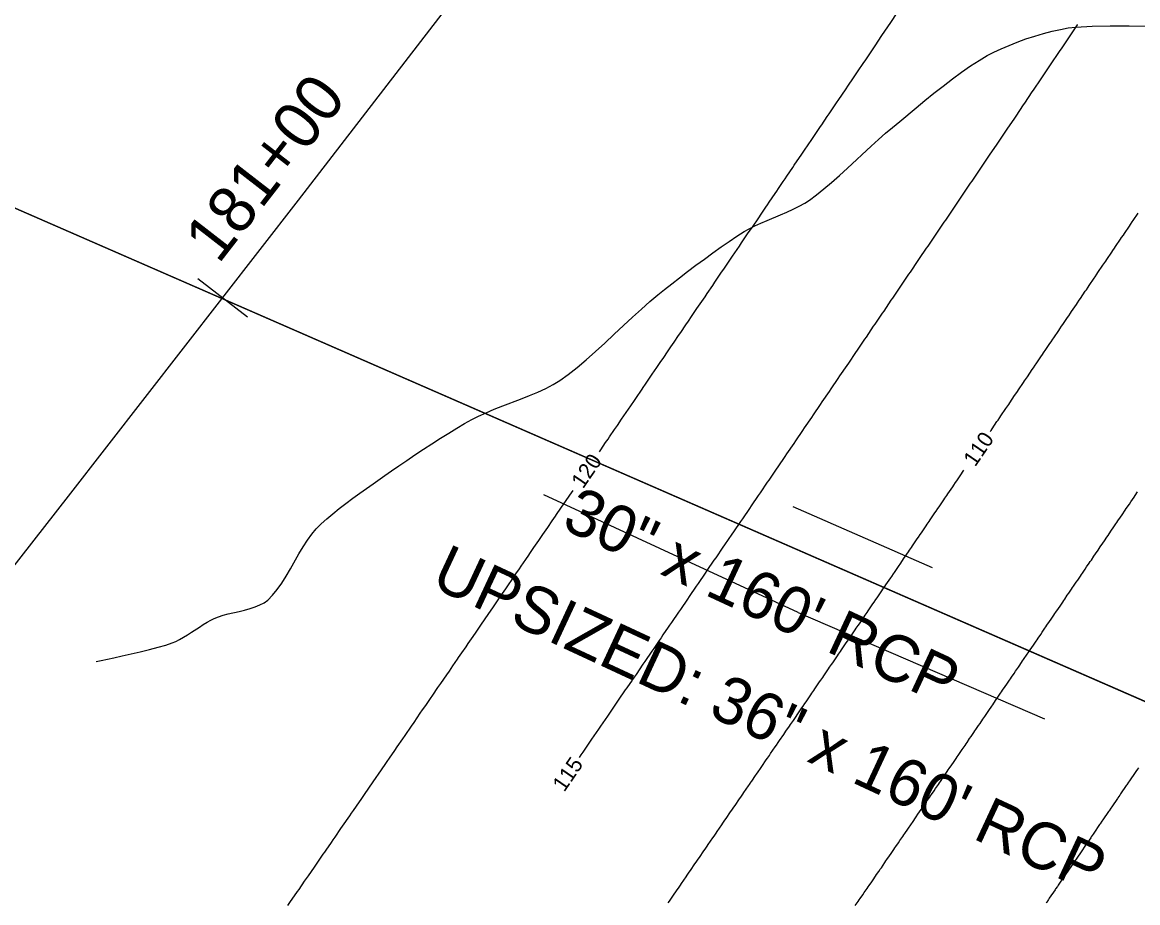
# Model space of a CAD drawing. Extents: x 1752788 to 1754108, y 472767 to 474963.
# Drawn here: x 1753208.6 to 1753280, y 473747.6 to 473804 of the extents above; entities that cross this region are included whole.
import ezdxf

# ---------------------------------------------------------------- set-up
doc = ezdxf.new("R2010")
doc.units = 0
for name, color, linetype in [('D_Drainage_Culvert', 7, 'Continuous'), ('D_Drainage_Text', 7, 'Continuous'), ('D_Roadway_Centerline', 7, 'Continuous'), ('D_Roadway_Centerline_Text', 7, 'Continuous'), ('Default', 7, 'Continuous'), ('M_Drainage_Ditch_Line', 7, 'Continuous'), ('S_Contours_Major', 7, 'Continuous')]:
    doc.layers.add(name, color=color, linetype=linetype)

msp = doc.modelspace()

# ---------------------------------------------------------------- linework, layer by layer
at = {"layer": 'D_Drainage_Culvert'}
for p, q in [((1753148.958, 473817.925), (1753295.6, 473753.923)), ((1753257.905, 473773.008), (1753266.845, 473769.099))]:
    msp.add_line(p, q, dxfattribs=at)
at = {"layer": 'D_Roadway_Centerline'}
msp.add_arc((1748084.974, 477769.754), 6500, 316.3419444, 334.4169444, dxfattribs=at)
at = {"layer": 'D_Roadway_Centerline_Text'}
msp.add_lwpolyline([(1753219.807, 473787.608), (1753222.968, 473785.156)], dxfattribs=at)
at = {"layer": 'Default'}
for p, q in [((1753295.6, 473753.923), (1753145.826, 473819.295)), ((1753258.251, 473766.217), (1753241.958, 473773.75)), ((1753258.251, 473766.217), (1753274.02, 473759.402))]:
    msp.add_line(p, q, dxfattribs=at)
at = {"layer": 'M_Drainage_Ditch_Line'}
msp.add_lwpolyline([(1753213.279, 473763.079), (1753213.598, 473763.144), (1753214.414, 473763.317), (1753214.944, 473763.433), (1753215.519, 473763.562), (1753216.113, 473763.702), (1753216.7, 473763.847), (1753217.255, 473763.993), (1753217.749, 473764.136), (1753218.159, 473764.272), (1753218.386, 473764.367), (1753218.625, 473764.488), (1753218.872, 473764.629), (1753219.126, 473764.785), (1753219.382, 473764.95), (1753219.895, 473765.288), (1753220.145, 473765.449), (1753220.389, 473765.599), (1753220.623, 473765.731), (1753220.846, 473765.841), (1753221.115, 473765.946), (1753221.418, 473766.039), (1753221.746, 473766.125), (1753222.443, 473766.29), (1753222.796, 473766.377), (1753223.141, 473766.472), (1753223.469, 473766.58), (1753223.773, 473766.703), (1753224.044, 473766.847), (1753224.274, 473767.015), (1753224.582, 473767.324), (1753224.88, 473767.692), (1753225.17, 473768.105), (1753225.452, 473768.552), (1753225.729, 473769.02), (1753226.275, 473769.97), (1753226.548, 473770.428), (1753226.822, 473770.857), (1753227.1, 473771.245), (1753227.384, 473771.581), (1753227.696, 473771.894), (1753228.051, 473772.216), (1753228.439, 473772.546), (1753228.853, 473772.878), (1753229.285, 473773.209), (1753229.726, 473773.537), (1753230.167, 473773.857), (1753230.602, 473774.165), (1753231.021, 473774.459), (1753231.78, 473774.99), (1753232.211, 473775.292), (1753232.682, 473775.617), (1753233.183, 473775.96), (1753233.706, 473776.314), (1753234.245, 473776.672), (1753234.79, 473777.029), (1753235.333, 473777.379), (1753235.868, 473777.715), (1753236.386, 473778.031), (1753236.878, 473778.321), (1753237.338, 473778.579), (1753237.776, 473778.8), (1753238.264, 473779.018), (1753238.789, 473779.234), (1753239.34, 473779.45), (1753240.475, 473779.888), (1753241.036, 473780.112), (1753241.579, 473780.341), (1753242.092, 473780.578), (1753242.563, 473780.823), (1753242.982, 473781.078), (1753243.521, 473781.463), (1753244.085, 473781.909), (1753244.669, 473782.401), (1753245.264, 473782.929), (1753245.866, 473783.479), (1753246.468, 473784.04), (1753247.064, 473784.599), (1753247.648, 473785.143), (1753248.212, 473785.66), (1753248.752, 473786.139), (1753249.262, 473786.566), (1753249.688, 473786.907), (1753250.153, 473787.274), (1753250.65, 473787.66), (1753251.169, 473788.058), (1753251.704, 473788.461), (1753252.247, 473788.863), (1753252.789, 473789.257), (1753253.322, 473789.636), (1753253.838, 473789.994), (1753254.33, 473790.324), (1753254.79, 473790.619), (1753255.11, 473790.803), (1753255.469, 473790.984), (1753255.857, 473791.162), (1753256.266, 473791.339), (1753257.11, 473791.693), (1753257.529, 473791.873), (1753257.934, 473792.055), (1753258.317, 473792.242), (1753258.668, 473792.435), (1753258.979, 473792.634), (1753259.429, 473792.968), (1753259.903, 473793.351), (1753260.394, 473793.771), (1753260.898, 473794.218), (1753261.407, 473794.684), (1753262.917, 473796.087), (1753263.396, 473796.523), (1753263.853, 473796.928), (1753264.284, 473797.29), (1753264.754, 473797.675), (1753265.803, 473798.544), (1753266.367, 473799.008), (1753266.948, 473799.478), (1753267.538, 473799.945), (1753268.13, 473800.4), (1753268.715, 473800.831), (1753269.288, 473801.231), (1753269.839, 473801.589), (1753270.363, 473801.896), (1753270.784, 473802.114), (1753271.252, 473802.334), (1753271.757, 473802.551), (1753272.289, 473802.761), (1753272.841, 473802.961), (1753273.401, 473803.146), (1753273.962, 473803.313), (1753274.515, 473803.458), (1753275.049, 473803.576), (1753275.556, 473803.664), (1753276.027, 473803.718), (1753277.088, 473803.779), (1753278.24, 473803.808), (1753279.464, 473803.81), (1753280.738, 473803.789)], dxfattribs=at)
at = {"layer": 'S_Contours_Major'}
for points in [[(1753245.517, 473776.51), (1753245.604, 473776.638), (1753245.92, 473777.101), (1753246.076, 473777.329), (1753246.169, 473777.466), (1753246.492, 473777.94), (1753246.674, 473778.206), (1753246.938, 473778.594), (1753247.24, 473779.036), (1753247.526, 473779.455), (1753247.764, 473779.805), (1753247.891, 473779.991), (1753248.208, 473780.457), (1753248.373, 473780.698), (1753248.428, 473780.779), (1753248.736, 473781.232), (1753248.907, 473781.482), (1753249.198, 473781.909), (1753249.46, 473782.295), (1753249.595, 473782.492), (1753249.923, 473782.974), (1753250.095, 473783.227), (1753250.312, 473783.546), (1753250.59, 473783.955), (1753250.73, 473784.16), (1753251.065, 473784.653), (1753251.225, 473784.887), (1753251.425, 473785.183), (1753251.768, 473785.686), (1753251.982, 473786.001), (1753252.284, 473786.445), (1753252.432, 473786.663), (1753252.777, 473787.171), (1753252.918, 473787.379), (1753253.348, 473788.011), (1753253.483, 473788.209), (1753253.918, 473788.851), (1753254.047, 473789.04), (1753254.488, 473789.691), (1753254.628, 473789.896), (1753255.059, 473790.531), (1753255.19, 473790.724), (1753255.319, 473790.914), (1753255.722, 473791.509), (1753255.875, 473791.733), (1753256.176, 473792.178), (1753256.287, 473792.341), (1753256.397, 473792.504), (1753256.768, 473793.051), (1753256.878, 473793.213), (1753256.986, 473793.372), (1753257.301, 473793.837), (1753257.415, 473794.005), (1753257.529, 473794.174), (1753257.907, 473794.731), (1753258.003, 473794.873), (1753258.479, 473795.576), (1753258.564, 473795.702), (1753258.651, 473795.83), (1753259.117, 473796.517), (1753259.206, 473796.65), (1753259.68, 473797.349), (1753259.761, 473797.469), (1753260.111, 473797.987), (1753260.234, 473798.168), (1753260.357, 473798.349), (1753260.752, 473798.934), (1753260.812, 473799.023), (1753261.321, 473799.775), (1753261.425, 473799.929), (1753261.796, 473800.477), (1753261.924, 473800.667), (1753262.052, 473800.856), (1753262.458, 473801.457), (1753262.533, 473801.568), (1753262.918, 473802.138), (1753263.049, 473802.333), (1753263.181, 473802.527), (1753263.618, 473803.175), (1753264.179, 473804.005), (1753264.6, 473804.63)], [(1753276.134, 473803.88), (1753276.12, 473803.859), (1753276.041, 473803.742), (1753275.558, 473803.025), (1753275.478, 473802.906), (1753275.088, 473802.328), (1753275.022, 473802.231), (1753274.927, 473802.089), (1753274.434, 473801.358), (1753274.352, 473801.236), (1753273.872, 473800.524), (1753273.789, 473800.401), (1753273.309, 473799.69), (1753273.226, 473799.566), (1753272.747, 473798.857), (1753272.662, 473798.731), (1753272.184, 473798.023), (1753272.099, 473797.896), (1753271.622, 473797.19), (1753271.535, 473797.062), (1753271.059, 473796.356), (1753270.971, 473796.227), (1753270.496, 473795.523), (1753270.407, 473795.393), (1753269.933, 473794.69), (1753269.843, 473794.558), (1753269.369, 473793.857), (1753269.279, 473793.724), (1753268.806, 473793.024), (1753268.715, 473792.89), (1753268.242, 473792.191), (1753268.15, 473792.055), (1753267.678, 473791.358), (1753267.586, 473791.221), (1753267.115, 473790.525), (1753267.021, 473790.387), (1753266.551, 473789.692), (1753266.456, 473789.553), (1753266.006, 473788.888), (1753265.926, 473788.771), (1753265.422, 473788.027), (1753265.326, 473787.885), (1753264.858, 473787.195), (1753264.761, 473787.052), (1753264.293, 473786.362), (1753264.196, 473786.218), (1753263.729, 473785.53), (1753263.63, 473785.385), (1753263.164, 473784.698), (1753263.065, 473784.551), (1753262.599, 473783.865), (1753262.499, 473783.718), (1753262.034, 473783.033), (1753261.933, 473782.884), (1753261.469, 473782.201), (1753261.367, 473782.051), (1753260.904, 473781.369), (1753260.801, 473781.218), (1753260.338, 473780.537), (1753260.234, 473780.385), (1753259.773, 473779.706), (1753259.668, 473779.552), (1753259.207, 473778.874), (1753259.101, 473778.719), (1753258.641, 473778.042), (1753258.535, 473777.886), (1753258.075, 473777.211), (1753257.968, 473777.053), (1753257.509, 473776.379), (1753257.401, 473776.221), (1753256.943, 473775.548), (1753256.84, 473775.398), (1753256.367, 473774.703), (1753256.268, 473774.558), (1753255.81, 473773.885), (1753255.699, 473773.723), (1753255.243, 473773.054), (1753255.131, 473772.891), (1753254.676, 473772.223), (1753254.564, 473772.058), (1753254.109, 473771.392), (1753253.996, 473771.226), (1753253.542, 473770.561), (1753253.428, 473770.394), (1753252.975, 473769.73), (1753252.86, 473769.562), (1753252.408, 473768.9), (1753252.292, 473768.73), (1753251.84, 473768.069), (1753251.724, 473767.898), (1753251.273, 473767.238), (1753251.155, 473767.066), (1753250.705, 473766.408), (1753250.586, 473766.235), (1753250.137, 473765.577), (1753250.018, 473765.403), (1753249.931, 473765.275), (1753249.591, 473764.779), (1753249.471, 473764.603), (1753249.351, 473764.428), (1753249.001, 473763.917), (1753248.88, 473763.74), (1753248.433, 473763.087), (1753248.311, 473762.908), (1753247.864, 473762.256), (1753247.742, 473762.077), (1753247.637, 473761.925), (1753247.615, 473761.892), (1753247.27, 473761.389), (1753247.178, 473761.254), (1753246.727, 473760.596), (1753246.603, 473760.415), (1753246.158, 473759.766), (1753246.033, 473759.584), (1753245.589, 473758.937), (1753245.463, 473758.753), (1753245.02, 473758.107), (1753244.893, 473757.922), (1753244.451, 473757.277), (1753244.323, 473757.091), (1753244.214, 473756.931)], [(1753270.55, 473777.805), (1753270.604, 473777.885), (1753270.674, 473777.988), (1753270.984, 473778.444), (1753271.054, 473778.547), (1753271.17, 473778.719), (1753271.24, 473778.822), (1753271.551, 473779.279), (1753271.62, 473779.382), (1753271.736, 473779.553), (1753271.806, 473779.655), (1753272.117, 473780.114), (1753272.186, 473780.216), (1753272.302, 473780.386), (1753272.372, 473780.489), (1753272.683, 473780.948), (1753272.752, 473781.05), (1753272.868, 473781.22), (1753272.937, 473781.323), (1753273.249, 473781.783), (1753273.318, 473781.885), (1753273.433, 473782.055), (1753273.502, 473782.156), (1753273.84, 473782.655), (1753273.865, 473782.691), (1753274.015, 473782.913), (1753274.081, 473783.01), (1753274.381, 473783.453), (1753274.45, 473783.554), (1753274.564, 473783.723), (1753274.633, 473783.824), (1753274.947, 473784.288), (1753275.015, 473784.389), (1753275.129, 473784.557), (1753275.198, 473784.658), (1753275.512, 473785.123), (1753275.581, 473785.224), (1753275.694, 473785.392), (1753275.763, 473785.493), (1753276.078, 473785.958), (1753276.146, 473786.059), (1753276.259, 473786.226), (1753276.327, 473786.327), (1753276.643, 473786.794), (1753276.711, 473786.894), (1753276.824, 473787.061), (1753276.892, 473787.161), (1753277.208, 473787.629), (1753277.276, 473787.729), (1753277.389, 473787.896), (1753277.456, 473787.996), (1753277.773, 473788.464), (1753277.841, 473788.564), (1753277.953, 473788.731), (1753278.021, 473788.83), (1753278.338, 473789.3), (1753278.405, 473789.399), (1753278.517, 473789.565), (1753278.585, 473789.665), (1753278.903, 473790.136), (1753278.97, 473790.235), (1753279.082, 473790.4), (1753279.149, 473790.5), (1753279.467, 473790.971), (1753279.534, 473791.07), (1753279.646, 473791.235), (1753279.713, 473791.334), (1753280.032, 473791.807)], [(1753249.93, 473747.621), (1753250.007, 473747.734), (1753250.137, 473747.923), (1753250.215, 473748.036), (1753250.501, 473748.453), (1753250.579, 473748.566), (1753250.708, 473748.754), (1753250.785, 473748.867), (1753251.072, 473749.285), (1753251.15, 473749.397), (1753251.278, 473749.585), (1753251.356, 473749.697), (1753251.643, 473750.116), (1753251.721, 473750.229), (1753251.849, 473750.416), (1753251.926, 473750.528), (1753252.215, 473750.948), (1753252.291, 473751.06), (1753252.419, 473751.247), (1753252.496, 473751.358), (1753252.785, 473751.78), (1753252.862, 473751.892), (1753252.99, 473752.078), (1753253.066, 473752.189), (1753253.356, 473752.612), (1753253.433, 473752.723), (1753253.56, 473752.909), (1753253.636, 473753.02), (1753253.927, 473753.444), (1753254.003, 473753.555), (1753254.13, 473753.74), (1753254.206, 473753.851), (1753254.497, 473754.276), (1753254.573, 473754.387), (1753254.7, 473754.572), (1753254.776, 473754.682), (1753255.074, 473755.118), (1753255.131, 473755.201), (1753255.244, 473755.366), (1753255.282, 473755.421), (1753255.52, 473755.768), (1753255.583, 473755.861), (1753255.686, 473756.012), (1753255.839, 473756.235), (1753255.915, 473756.345), (1753256.208, 473756.773), (1753256.284, 473756.883), (1753256.409, 473757.067), (1753256.485, 473757.177), (1753256.778, 473757.606), (1753256.853, 473757.716), (1753256.979, 473757.899), (1753257.054, 473758.009), (1753257.327, 473758.408), (1753257.465, 473758.61), (1753257.693, 473758.943), (1753257.768, 473759.052), (1753257.943, 473759.308), (1753258.117, 473759.562), (1753258.191, 473759.671), (1753258.487, 473760.104), (1753258.562, 473760.213), (1753258.686, 473760.394), (1753258.76, 473760.503), (1753259.057, 473760.937), (1753259.131, 473761.045), (1753259.255, 473761.226), (1753259.329, 473761.335), (1753259.626, 473761.77), (1753259.7, 473761.878), (1753259.823, 473762.058), (1753259.897, 473762.167), (1753260.195, 473762.603), (1753260.269, 473762.711), (1753260.392, 473762.891), (1753260.466, 473762.999), (1753260.764, 473763.436), (1753260.838, 473763.543), (1753260.961, 473763.723), (1753261.034, 473763.831), (1753261.333, 473764.269), (1753261.407, 473764.376), (1753261.529, 473764.555), (1753261.602, 473764.663), (1753261.902, 473765.102), (1753261.975, 473765.209), (1753262.097, 473765.388), (1753262.17, 473765.495), (1753262.471, 473765.935), (1753262.544, 473766.042), (1753262.665, 473766.221), (1753262.738, 473766.328), (1753263.039, 473766.769), (1753263.112, 473766.875), (1753263.233, 473767.053), (1753263.306, 473767.16), (1753263.607, 473767.602), (1753263.68, 473767.709), (1753263.801, 473767.886), (1753263.874, 473767.992), (1753264.178, 473768.439), (1753264.243, 473768.534), (1753264.351, 473768.693), (1753264.416, 473768.787), (1753264.713, 473769.224), (1753264.778, 473769.319), (1753264.936, 473769.552), (1753265.008, 473769.658), (1753265.312, 473770.103), (1753265.384, 473770.209), (1753265.504, 473770.385), (1753265.576, 473770.49), (1753265.88, 473770.937), (1753265.951, 473771.042), (1753266.071, 473771.218), (1753266.143, 473771.323), (1753266.447, 473771.771), (1753266.519, 473771.876), (1753266.638, 473772.051), (1753266.71, 473772.156), (1753267.015, 473772.605), (1753267.086, 473772.709), (1753267.205, 473772.884), (1753267.276, 473772.989), (1753267.582, 473773.439), (1753267.653, 473773.543), (1753267.772, 473773.717), (1753267.843, 473773.822), (1753268.15, 473774.273), (1753268.22, 473774.377), (1753268.339, 473774.551), (1753268.41, 473774.655), (1753268.717, 473775.107), (1753268.787, 473775.211), (1753268.871, 473775.333)], [(1753225.57, 473747.452), (1753225.698, 473747.638), (1753226.189, 473748.348), (1753226.279, 473748.479), (1753226.638, 473749), (1753226.76, 473749.176), (1753226.882, 473749.353), (1753227.268, 473749.912), (1753227.353, 473750.035), (1753227.834, 473750.733), (1753227.925, 473750.866), (1753228.02, 473751.003), (1753228.357, 473751.492), (1753228.473, 473751.661), (1753228.59, 473751.829), (1753228.965, 473752.374), (1753229.071, 473752.527), (1753229.53, 473753.194), (1753229.643, 473753.358), (1753229.76, 473753.527), (1753230.152, 473754.097), (1753230.253, 473754.243), (1753230.473, 473754.563), (1753230.756, 473754.974), (1753230.8, 473755.038), (1753231.226, 473755.657), (1753231.36, 473755.852), (1753231.79, 473756.478), (1753231.932, 473756.683), (1753232.077, 473756.895), (1753232.415, 473757.385), (1753232.57, 473757.611), (1753232.92, 473758.12), (1753233.075, 473758.346), (1753233.484, 473758.941), (1753233.647, 473759.177), (1753234.049, 473759.762), (1753234.197, 473759.978), (1753234.393, 473760.263), (1753234.697, 473760.706), (1753234.842, 473760.917), (1753235.177, 473761.405), (1753235.36, 473761.672), (1753235.741, 473762.226), (1753235.908, 473762.469), (1753236.128, 473762.791), (1753236.427, 473763.227), (1753236.503, 473763.338), (1753236.706, 473763.633), (1753236.977, 473764.028), (1753237.111, 473764.223), (1753237.432, 473764.691), (1753237.617, 473764.961), (1753237.968, 473765.473), (1753238.159, 473765.752), (1753238.44, 473766.162), (1753238.686, 473766.521), (1753238.812, 473766.704), (1753239.122, 473767.157), (1753239.318, 473767.444), (1753239.519, 473767.737), (1753239.742, 473768.063), (1753239.88, 473768.264), (1753240.172, 473768.691), (1753240.393, 473769.014), (1753240.511, 473769.186), (1753240.81, 473769.623), (1753241.001, 473769.901), (1753241.064, 473769.994), (1753241.326, 473770.377), (1753241.535, 473770.683), (1753241.635, 473770.829), (1753241.903, 473771.221), (1753242.1, 473771.508), (1753242.209, 473771.669), (1753242.498, 473772.09), (1753242.704, 473772.392), (1753242.773, 473772.492), (1753243.057, 473772.908), (1753243.237, 473773.171), (1753243.341, 473773.324), (1753243.619, 473773.731), (1753243.832, 473774.042)], [(1753261.913, 473747.439), (1753262.099, 473747.711), (1753262.164, 473747.805), (1753262.228, 473747.898), (1753262.388, 473748.132), (1753262.484, 473748.273), (1753262.67, 473748.543), (1753262.734, 473748.637), (1753262.799, 473748.731), (1753262.962, 473748.97), (1753263.05, 473749.098), (1753263.202, 473749.319), (1753263.274, 473749.425), (1753263.419, 473749.636), (1753263.514, 473749.775), (1753263.579, 473749.87), (1753263.812, 473750.209), (1753263.876, 473750.303), (1753263.94, 473750.397), (1753264.101, 473750.632), (1753264.198, 473750.773), (1753264.382, 473751.043), (1753264.447, 473751.137), (1753264.511, 473751.231), (1753264.672, 473751.466), (1753264.769, 473751.607), (1753264.953, 473751.876), (1753265.018, 473751.97), (1753265.082, 473752.065), (1753265.275, 473752.347), (1753265.501, 473752.677), (1753265.565, 473752.771), (1753265.807, 473753.124), (1753265.923, 473753.294), (1753266.124, 473753.588), (1753266.189, 473753.683), (1753266.384, 473753.967), (1753266.481, 473754.109), (1753266.662, 473754.374), (1753266.727, 473754.469), (1753266.792, 473754.564), (1753266.954, 473754.801), (1753267.051, 473754.943), (1753267.232, 473755.207), (1753267.297, 473755.302), (1753267.362, 473755.397), (1753267.524, 473755.635), (1753267.622, 473755.777), (1753267.802, 473756.041), (1753267.867, 473756.136), (1753267.932, 473756.231), (1753268.094, 473756.469), (1753268.192, 473756.612), (1753268.371, 473756.874), (1753268.436, 473756.969), (1753268.501, 473757.065), (1753268.664, 473757.303), (1753268.762, 473757.446), (1753268.94, 473757.707), (1753269.006, 473757.803), (1753269.071, 473757.898), (1753269.234, 473758.137), (1753269.332, 473758.28), (1753269.51, 473758.541), (1753269.575, 473758.637), (1753269.64, 473758.732), (1753269.803, 473758.971), (1753269.901, 473759.115), (1753270.079, 473759.375), (1753270.144, 473759.47), (1753270.209, 473759.566), (1753270.373, 473759.806), (1753270.471, 473759.949), (1753270.648, 473760.208), (1753270.713, 473760.304), (1753270.779, 473760.4), (1753270.942, 473760.64), (1753271.04, 473760.784), (1753271.216, 473761.042), (1753271.282, 473761.138), (1753271.348, 473761.234), (1753271.511, 473761.475), (1753271.61, 473761.619), (1753271.785, 473761.876), (1753271.851, 473761.972), (1753271.916, 473762.069), (1753272.08, 473762.309), (1753272.179, 473762.454), (1753272.358, 473762.716), (1753272.446, 473762.845), (1753272.63, 473763.116), (1753272.689, 473763.202), (1753272.922, 473763.544), (1753272.988, 473763.641), (1753273.054, 473763.737), (1753273.218, 473763.979), (1753273.317, 473764.124), (1753273.49, 473764.378), (1753273.556, 473764.475), (1753273.622, 473764.572), (1753273.787, 473764.813), (1753273.886, 473764.959), (1753274.058, 473765.212), (1753274.124, 473765.309), (1753274.19, 473765.406), (1753274.355, 473765.648), (1753274.454, 473765.794), (1753274.626, 473766.046), (1753274.693, 473766.144), (1753274.759, 473766.241), (1753274.924, 473766.483), (1753275.023, 473766.629), (1753275.194, 473766.881), (1753275.261, 473766.978), (1753275.327, 473767.075), (1753275.492, 473767.318), (1753275.591, 473767.464), (1753275.762, 473767.715), (1753275.828, 473767.813), (1753275.895, 473767.91), (1753276.06, 473768.154), (1753276.16, 473768.3), (1753276.33, 473768.55), (1753276.396, 473768.647), (1753276.462, 473768.745), (1753276.628, 473768.989), (1753276.728, 473769.135), (1753276.897, 473769.384), (1753276.964, 473769.482), (1753277.03, 473769.58), (1753277.196, 473769.824), (1753277.296, 473769.971), (1753277.464, 473770.219), (1753277.531, 473770.317), (1753277.597, 473770.415), (1753277.764, 473770.659), (1753277.863, 473770.806), (1753278.032, 473771.054), (1753278.098, 473771.152), (1753278.165, 473771.25), (1753278.331, 473771.495), (1753278.431, 473771.642), (1753278.599, 473771.889), (1753278.665, 473771.987), (1753278.732, 473772.085), (1753278.899, 473772.33), (1753278.999, 473772.478), (1753279.199, 473772.773), (1753279.266, 473772.871), (1753279.466, 473773.166), (1753279.566, 473773.314), (1753279.766, 473773.608), (1753279.833, 473773.706), (1753279.994, 473773.943)], [(1753280.046, 473756.271), (1753279.989, 473756.189), (1753279.876, 473756.023), (1753279.839, 473755.968), (1753279.475, 473755.435), (1753279.419, 473755.353), (1753279.307, 473755.188), (1753279.269, 473755.133), (1753278.905, 473754.599), (1753278.849, 473754.517), (1753278.737, 473754.352), (1753278.699, 473754.297), (1753278.335, 473753.764), (1753278.279, 473753.681), (1753278.167, 473753.517), (1753278.129, 473753.462), (1753277.764, 473752.928), (1753277.708, 473752.846), (1753277.596, 473752.682), (1753277.559, 473752.627), (1753277.194, 473752.092), (1753277.138, 473752.011), (1753277.026, 473751.847), (1753276.989, 473751.792), (1753276.623, 473751.257), (1753276.567, 473751.175), (1753276.456, 473751.012), (1753276.418, 473750.957), (1753276.052, 473750.421), (1753275.996, 473750.34), (1753275.885, 473750.177), (1753275.848, 473750.123), (1753275.481, 473749.586), (1753275.426, 473749.505), (1753275.314, 473749.342), (1753275.277, 473749.288), (1753274.91, 473748.751), (1753274.854, 473748.67), (1753274.744, 473748.507), (1753274.707, 473748.453), (1753274.339, 473747.916), (1753274.283, 473747.834), (1753274.172, 473747.672), (1753274.135, 473747.618)]]:
    msp.add_lwpolyline(points, dxfattribs=at)

# ---------------------------------------------------------------- texts
at = {"layer": 'D_Drainage_Text'}
for s, p in [('30" x 160\' RCP', (1753243.001, 473771.657)), ('UPSIZED: 36" x 160\' RCP', (1753234.617, 473767.93))]:
    msp.add_text(s, height=2.99999, rotation=335.05419, dxfattribs=at).set_placement(p)
at = {"layer": 'D_Roadway_Centerline_Text'}
msp.add_text('181+00', height=3, rotation=52.20585, dxfattribs=at).set_placement((1753221.122, 473788.487))
at = {"layer": 'S_Contours_Major'}
for s, rotation, p in [('110', 55.80788, (1753269.59, 473775.505)), ('120', 55.67455, (1753244.474, 473774.1)), ('115', 55.52604, (1753243.267, 473754.672))]:
    msp.add_text(s, height=0.996, rotation=rotation, dxfattribs=at).set_placement(p)

doc.saveas('drawing.dxf')
